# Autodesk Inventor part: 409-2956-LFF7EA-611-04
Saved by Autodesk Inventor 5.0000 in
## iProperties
Created: 2010-06
Part Number: 409-2956-LFF7EA-611-04
Cost Center: 0 lbmass
Material: A36 STEEL PLATE
Document SubType Name: Sheet Metal
Designer: S. Boerckel
Authority: 0 in^3
Mass: 83350.1 g
Surface Area: 17214 cm^2
Volume: 10604.3 cm^3
Density: 7.86 g/cm^3
Flat Pattern Width: 68.58 cm
Flat Pattern Length: 121.92 cm
Flat Pattern Area: 8361.27 cm^2
Sheet Metal Rule: 1/2"Thk
Sheet Metal Width: 16.0000 in
Sheet Metal Length: 80.0000 in^2
Description: PUMP FOOT PLATE
User Status: BURN
SaveDate: 2008-01-15
SaveTime: 10:24
FileName: Sheet Metal
Wide: =<Flat Pattern Width>cm
Length: =<Flat Pattern Length>cm
Thickness: 0.5000 in
SMR: =<Sheet Metal Rule> - <Material>
Author: S. Boerckel
Revision Number: 0
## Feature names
1. Hole1
2. Plate1
